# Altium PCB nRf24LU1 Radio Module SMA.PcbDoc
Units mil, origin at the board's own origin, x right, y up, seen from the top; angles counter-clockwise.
Board outline 2945.94 x 691.05 mil, 2 copper layers (Top Layer, Bottom Layer); 43 components, 43 nets, 167 pads, 126 vias.
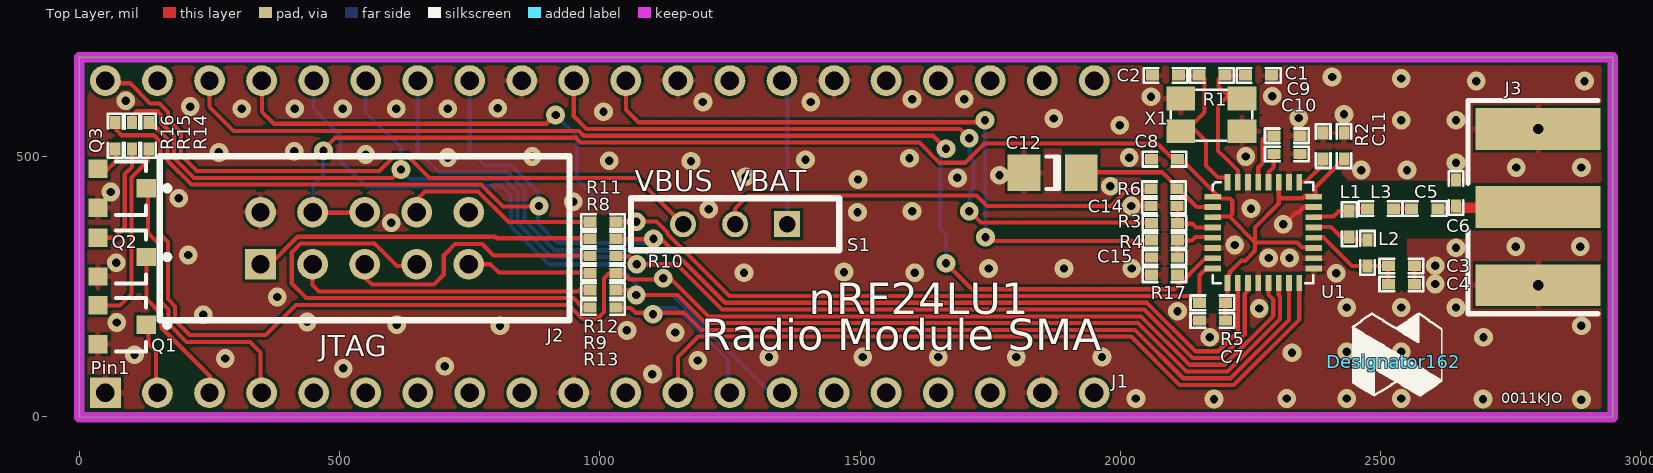
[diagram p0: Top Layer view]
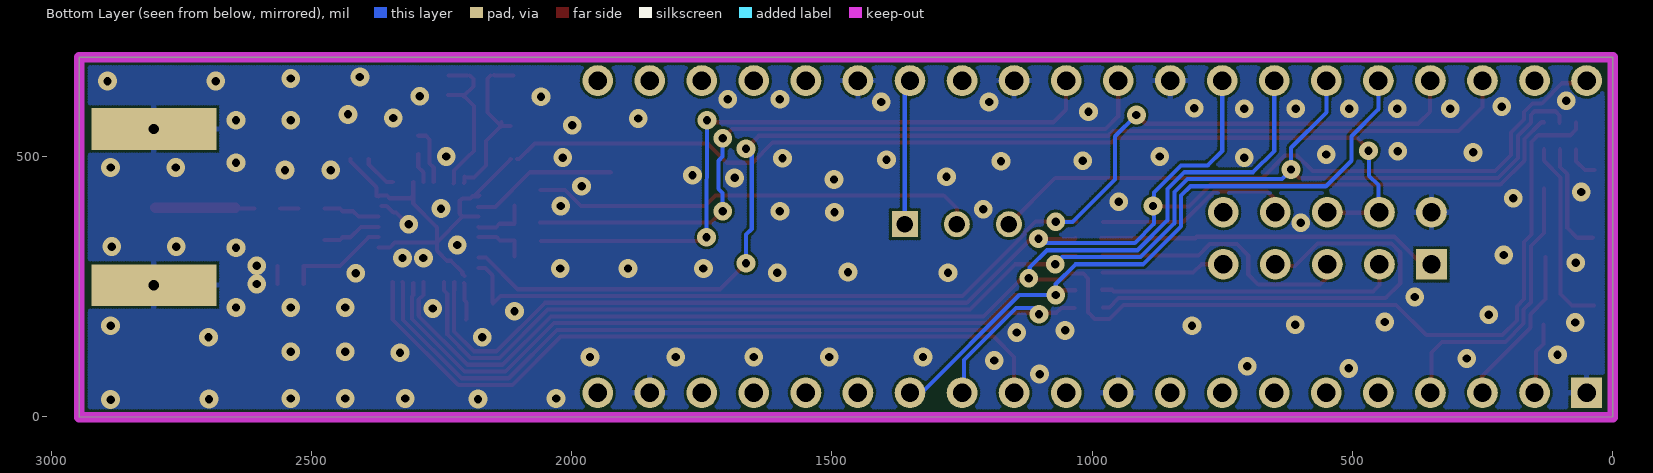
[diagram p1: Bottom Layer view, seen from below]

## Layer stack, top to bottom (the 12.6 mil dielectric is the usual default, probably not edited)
Top Layer: signal copper 1.4
Dielectric: dielectric 12.6, FR-4, Dk 4.8
Bottom Layer: signal copper 1.4

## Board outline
0,0 0,690.53 2945.94,690.53 2945.94,-0.53

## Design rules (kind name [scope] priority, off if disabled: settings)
Clearance [All] p1: gap=5
ComponentClearance [All] p1 off: gap=10 collisioncheckmode=3 verticalgap=10
PolygonConnect PolygonConnect_1 [IsVia and InNet(GND)] p1: connectstyle=Direct reliefconductorwidth=10 reliefentries=4 polygonreliefangle="90 Angle"
PolygonConnect [All] p2: connectstyle=Relief reliefconductorwidth=10 reliefentries=4 polygonreliefangle="90 Angle"
RoomDefinition "nRF24LU1 Radio Module SMA" [InComponentClass('nRF24LU1 Radio Module SMA')] p1 off: confinementstyle=ConfineIn formatcopy=TRUE lockcomponents=FALSE outline 3275,-45 3549,-45 3549,486 3275,486
RoutingVias [All] p1: holewidth=10 width=20 viastyle="Through Hole" minholewidth=6 minwidth=10 maxholewidth=28 maxwidth=50
SolderMaskExpansion [All] p1: expansion=4
TestPointUsage [All] p1: valid=0 allowmultiple=FALSE
Testpoint [All] p1: side=15 testpointundercomponent=TRUE minsize=40 maxsize=100 preferedsize=60 minholesize=0 maxholesize=40 preferedholesize=32 testpointgrid=1 style=1023 order=0123456789
Width [All] p1: maxlimit=50 minlimit=6 preferedwidth=10 toplayer_prefwidth=8 bottomlayer_prefwidth=8 minimp=50.000000 maximp=50.000000 favimp=50.000000
18 further rules are at their usual default settings.

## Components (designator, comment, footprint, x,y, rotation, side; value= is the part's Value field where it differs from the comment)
C1 "NPO, +/-2% 50V" 0402s 2266,656 r0 top
C2 "NPO, +/-2% 50V" 0402s 2087,656 r0 top
C3 "X7R, +/-10% 50V" 0402s 2540,290 r180 top
C4 "NP0 +/-0.25pF, 50V" 0402s 2540,255 r180 top
C5 "NP0 +/-0.1pF, 50V" 0402s 2585,400 r180 top
C6 "NP0 +/-0.1pF, 50V" 0402s 2645,430 r90 top
C7 "X7R, +/-10% 50V" 0402s 2177,185 r180 top
C8 "X7R, +/-10% 50V" 0402s 2085,495 r180 top
C9 "X7R, +/-10% 50V" 0402s 2320,540 r0 top
C10 "X7R, +/-10% 50V" 0402s 2320,505 r0 top
C11 "X7R, +/-10% 50V" 0402s 2430,520 r90 top
C12 "Tantal  10V" C1206 1870,469 r180 top
C14 "NP0, +/-10% 50V" 0402s 2084,405 r180 top
C15 "" 0402s 2085,306 r180 top
Designator162 "Comment" NordicSemi1 2525,106 r180 top
J1 "Elfa 48-155-10" DIP40 50,46 r90 top
J2 "Header 2x5 pin" IDC2X5 548,343 r0 top
J3 "SMA Female" "SMA connector horizontal" 2803,403 r90 top
L1 "Chip inductor +/-5% Murata LQP15" 0402s 2440,370 r270 top
L2 "Chip Inductor +/-5% Murata LQP15" 0402s 2475,315 r90 top
L3 "Chip inductor +/-5% Murata LQP15" 0402s 2500,400 r0 top
Q1 "BC847C" SOT23 82,177 r270 top
Q2 "BC847C" SOT23 82,307 r270 top
Q3 "BC847C" SOT23 82,439 r270 top
R1 "5%" 0402s 2176,656 r180 top
R2 "1%" 0402s 2390,520 r270 top
R3 "5%" 0402s 2085,372 r180 top
R4 "5%" 0402s 2085,339 r180 top
R5 "5%" 0402s 2177,219 r0 top
R6 "5%" 0402s 2084,438 r180 top
R8 "" 0402s 1006,342 r180 top
R9 "" 0402s 1006,243 r180 top
R10 "" 0402s 1006,309 r180 top
R11 "" 0402s 1006,375 r180 top
R12 "" 0402s 1006,276 r180 top
R13 "" 0402s 1006,210 r180 top
R14 "5%" 0402s 133,540 r270 top
R15 "5%" 0402s 101,540 r270 top
R16 "5%" 0402s 69,540 r270 top
R17 "5%" 0402s 2085,273 r0 top
S1 "ELFA 35-365-21" "SW mini2" 1360,370 r180 top
U1 "nRF24LU1" QFN32L/5x5 2178,257 r0 top
X1 "TSX4025 16MHz, CL=9pF" BT-XTAL 2175,580 r180 top

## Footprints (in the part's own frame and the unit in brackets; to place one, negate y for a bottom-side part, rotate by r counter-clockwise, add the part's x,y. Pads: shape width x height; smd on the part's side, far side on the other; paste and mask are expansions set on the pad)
0402s [mil]
  rect 25x20 smd: 1(-25,0) 2(25,0)
  silkscreen extent -42,-14 42,14
BT-XTAL [mm]
  rect 1.4x1.15 smd: 1(-1.498,-0.801) 2(1.498,-0.801) 3(1.498,0.801) 4(-1.498,0.801)
  silkscreen extent -2,-1.23 1.98,1.26
C1206 [mm] "Chip Capacitor; Body 3.2 x 1.6 mm (LxW typ)"
  rect 1.6x1.8 smd: 1(-1.4,0) 2(1.4,0)
  silkscreen extent -0.3,-0.8 0.3,0.8
DIP40 [mm]
  rect 1.5x1.5 hole 0.9: 1(0,0)
  round 1.5 hole 0.9: 2(0,-2.54) 3(0,-5.08) 4(0,-7.62) 5(0,-10.16) 6(0,-12.7) 7(0,-15.24) 8(0,-17.78) 9(0,-20.32) 10(0,-22.86) 11(0,-25.4) 12(0,-27.94) 13(0,-30.48) 14(0,-33.02) 15(0,-35.56) 16(0,-38.1) 17(0,-40.64) 18(0,-43.18) 19(0,-45.72) 20(0,-48.26) 21(15.24,-48.26) 22(15.24,-45.72) 23(15.24,-43.18) 24(15.24,-40.64) 25(15.24,-38.1) 26(15.24,-35.56) 27(15.24,-33.02) 28(15.24,-30.48) 29(15.24,-27.94) 30(15.24,-25.4) 31(15.24,-22.86) 32(15.24,-20.32) 33(15.24,-17.78) 34(15.24,-15.24) 35(15.24,-12.7) 36(15.24,-10.16) 37(15.24,-7.62) 38(15.24,-5.08) 39(15.24,-2.54) 40(15.24,0)
IDC2X5 [mm]
  rect 1.5x1.5 hole 0.9: 1(-5.08,-1.27)
  round 1.5 hole 0.9: 2(-5.08,1.27) 3(-2.54,-1.27) 4(-2.54,1.27) 5(0,-1.27) 6(0,1.27) 7(2.54,-1.27) 8(2.54,1.27) 9(5.08,-1.27) 10(5.08,1.27)
  silkscreen extent -10,-4 10,4
NordicSemi1 [mil]
  silkscreen extent -94,-94 80,66
QFN32L/5x5 [mm]
  rect 0.8x0.28 smd: 1(-0.001,4.205) 2(-0.001,3.705) 3(-0.001,3.205) 4(-0.001,2.705) 5(-0.001,2.205) 6(-0.001,1.705) 7(-0.001,1.205) 8(-0.001,0.705) 17(4.917,0.705) 18(4.917,1.205) 19(4.917,1.705) 20(4.917,2.205) 21(4.917,2.705) 22(4.917,3.205) 23(4.917,3.705) 24(4.917,4.205)
  rect 0.28x0.8 smd: 9(0.71,0) 10(1.21,0.004) 11(1.71,0.004) 12(2.21,0.004) 13(2.71,0.004) 14(3.21,0.004) 15(3.71,0.004) 16(4.21,0.004) 25(4.21,4.921) 26(3.71,4.921) 27(3.21,4.921) 28(2.71,4.921) 29(2.21,4.921) 30(1.71,4.921) 31(1.21,4.921) 32(0.71,4.921)
  silkscreen extent 0,-0.01 4.9,4.92
"SMA connector horizontal" [mil]
  rect 80x240 smd: 1(0,0)
  rect 80x240 hole 20: 2(-150,0) 2(150,0)
  silkscreen extent -205,-115 205,135
SOT23 [mm] "SOT-23; 3 Leads; Body 3.1 x 2.5 mm, inc. leads (LxW max), Alternate Lead Configuration"
  rect 0.9x0.95 smd: 1(0,1.175) 2(0.95,-1.175) 3(-0.95,-1.175)
  silkscreen extent -1.3,-0.3 1.3,2.33
"SW mini2" [mil]
  rect 50x50 hole 32: 1(0,0)
  round 50 hole 32: 2(100,0) 3(200,0)
  silkscreen extent -100,-50 300,50

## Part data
C1 C2 C3 C4 C5 C6 C7 C8 C9 C10 C11 C14 C15: library part CAP
C12: library part "Cap Pol3", "Polarized Capacitor (Surface Mount)"
J1: library part 40PIN
J2: library part "Header 6", "Header, 6-Pin"
J3: library part BNC, "BNC Elbow Connector"
L1 L2 L3: library part INDUCTOR1
Q1 Q2 Q3: library part NPN, "NPN Bipolar Transistor"
R1 R2 R3 R4 R5 R6 R8 R9 R10 R11 R12 R13 R14 R15 R16 R17: library part RES2
S1: library part SW-SPDT, "SPDT Subminiature Toggle Switch, Right Angle Mounting, Vertical Actuation"
U1: library part nRF24LU01, "nRF24LU01"
X1: library part BT-XTAL

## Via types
v1: diameter 36, hole 16, Top Layer to Bottom Layer, tented both sides, 125 vias
v2: diameter 35.98, hole 15.98, Top Layer to Bottom Layer, tented both sides, 1 vias

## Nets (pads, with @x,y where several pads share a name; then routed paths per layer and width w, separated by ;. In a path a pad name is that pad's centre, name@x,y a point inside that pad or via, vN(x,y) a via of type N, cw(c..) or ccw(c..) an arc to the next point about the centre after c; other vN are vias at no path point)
CSN/TDO: J1.14 J1.36 R9.1 U1.14 | length 2706.7
  Top Layer w8: R9.1@1032,243 1061,243 v1(1070,234) 1149,234 1203,180 2034,180 2127,87 2206,87 2307,188 2307,231 2304,234 ; 2304.53,234.53 U1.14@2304.53,257.15
  Bottom Layer w7.99: 829,366 829,425
  Bottom Layer w8: J1.36@450,645 450,591 502,539 502,492 551,443 811,443 829,425 ; 829,366 902,293 1032,293 1070,255 v1(1070,234) 1140,234 1329,45 1348,45 J1.14@1350,47
D+: J1.31 R3.2 | length 1351.8
  Top Layer w8: J1.31@950,645 950,577.5 974.5,553 1692,553 v1(1710,535) ; v1(1710,395) 1732,373 R3.2@2061,373
  Bottom Layer w8: v1(1710,395) 1710,430 1718,438 1718,492 1710,500 v1(1710,535)
D-: J1.30 R4.2 | length 1306.3
  Top Layer w8: J1.30@1050,645 1050,590 1074,566 1736,566 v1(1740,570) ; v1@1738,347 1747,338 R4.2@2059,338
  Bottom Layer w8: v1(1740,570) v1@1740.9,345
  other v1: 1741,345
GND: C1.2 C2.1 C3.1 C4.1 C6.2 C7.2 C8.2 C9.2 C10.2 C11.2 C12.2 C14.2 C15.2 J1.1 J1.10 J1.19 J1.26 J1.29 J1.32 J2.2 J3.2 Q1.2 Q2.2 Q3.2 R2.1 R17.1 U1.6 U1.12 U1.17 U1.18 U1.23 U1.26 U1.30 X1.2 X1.4 | length 85.4
  Top Layer w8: v1@2325,380 2337.53,392.53 2342.89,392.53 2355.36,405 U1.23@2365,405 ; C4.1 C3.1
  other v1: 2886,33 2180,34 2697,34 2030,35 2320,35 2435,35 2540,35 1101,82 507,93 702,97 1188,108 280,112 1325,115 1505,115 1650,115 1800,115 1965,115 106,119 2330,123 2435,125 2540,125 2172,153 2698,153 1145,162 1052,166 808,175 2886,175 610,177 72,181 438,182 238,196 2110,203 2267,208 2435,210 2540,210 2645,210 380,230 2605,255 2415,276 1277,277 1605,277 1469,278 1747,285 1892,285 2022,285 2605,290 2285,305 2325,305 209,311 2645,325 2760,327 2884,327 2220,330 2313,370 599,373 1495,393 1600,395 1209,399 2251,400 2021,405 949,413 191,420 60,432 1981,443 1496,456 1687,459 1280,461 1768,464 2463,474 2551,474 2761,479 2886,479 2645,488 1175,491 1018,492 1395,494 1595,497 708,498 2017,498 870,500 2241,500 550,504 268,508 413,510 1999,560 2540,570 2645,570 1872,573 2343,574 2430,581 1007,586 312,592 414,592 506,592 609,592 708,592 804,593 213,596 1198,605 1405,605 89,607 1600,610 1700,610 2059,615 2292,616 2684,645 2892,645 2540,650 2407,653
  other v2: 71,296
LED1: J1.2 Q1.1 | length 135.8
  Top Layer w8: Q1.1@133,177 133,140 147,126 J1.2@147,47
LED2: J1.3 Q2.1 | length 310.9
  Top Layer w8: Q2.1@129,307 129,226 158,197 158,171 252,77 J1.3@252,47
LED3: J1.4 Q3.1 | length 552.6
  Top Layer w8: Q3.1@132,438 132,353 157,328 157,220 171,206 171,179 206,144 328,144 348.26,123.74 348.26,48.26 J1.4@347,47
LED4: J1.5
MISO/TDI: J1.34 R12.1 R16.1 U1.13 | length 3618.5
  Top Layer w8: R16.1@70,565 70,552 81,541 143,541 156,528 156,350 170,336 170,226 184,212 184,185 212,157 358,157 416,215 940,215 967,188 995,188 1008,201 1008,266 1017,275 1046,275 1057,264 1138,264 1209,193 2040,193 2133,100 2200,100 2294,194 2294,225 2284.84,234.16 U1.13@2284.84,258.89
  Bottom Layer w8: J1.34@650,645 650,511 691,470 822.75,470 855,437.75 855,377.75 912.75,320 1087,320 1120,287 v1@1120,275
  other v1: 1122,266
MOSI/TMS: J1.35 R10.1 R15.1 U1.11 | length 2805.3
  Top Layer w7.99: R15.1@102,565 102,579 110,587 150,587
  Top Layer w8: 150,587 157,580 157,565 182,540 182,497.44 220.44,459 602,459 v1@618.5,475.5 ; R10.1 1056,309 1072,293 1148,293 1235,206 2046,206 2139,113 2194,113 2239,158 2239,236.06 2245.47,242.53 U1.11@2245.47,258.89
  Bottom Layer w8: J1.35@550,645 550,585 618,517 v1@618,476 ; v1@617,476 617,475 635,457 817,457 842,432 842,372 907,307 1058,307 v1@1074,291
  other v1: 1071,293 618,475
NetC1_1: C1.1 R1.1 U1.31 X1.1 | length 309.2
  Top Layer w8: R1.1@2196,656 2189,649 2189,635 X1.1@2208,616 ; R1.1 C1.1@2237,656 ; 2202,497 2188,511 2188,597 2209,618 X1.1@2238,618 ; 2203,496 2226,473 2226,449 U1.31@2227,448
NetC2_2: C2.2 R1.2 U1.32 X1.3 | length 335.8
  Top Layer w8: C2.2 2148,656 R1.2@2149,657 ; X1.3@2118,559 2136,559 2165,530 2165,483 2188,460 2206,460 2206,450 U1.32@2207,449 ; X1.3@2135,566 2135,558 2162,585 2162,650 R1.2@2156,656 ; U1.32@2206.1,451.11 U1.32@2206.1,461.9
NetC3_2: C3.2 C4.2 L2.1 U1.20 | length 201.7
  Top Layer w8: U1.20@2371.11,345.16 2389.84,345.16 2445,290 C3.2 C4.2
NetC5_1: C5.1 C6.1 J3.1 | length 191.1
  Top Layer w8: C5.1 2640,400 C6.1
  Top Layer w20: C6.1@2646,402 J3.1@2800,402
NetC5_2: C5.2 L3.2 | length 35
  Top Layer w8: L3.2 C5.2
NetC9_1: C9.1 U1.29 | length 110
  Top Layer w8: U1.29@2265.16,451.11 2265.16,479.16 2273,487 2273,533 2280,540 C9.1
NetC10_1: C10.1 U1.28 | length 58.1
  Top Layer w8: U1.28@2284.84,451.11 2284.84,469.84 2295,480 C10.1
NetC12_1: C12.1 R6.1 U1.2 | length 282.8
  Top Layer w8: C12.1@1925,470 2080,470 2147,403 U1.2@2180,403
NetC14_1: C14.1 R3.1 U1.4 | length 107.1
  Top Layer w8: C14.1@2110,406 2110,371 2138.68,371 2145.68,364 U1.4@2177.96,364 ; U1.4@2178.05,364 U1.4@2178.89,364.84
NetC15_1: C15.1 R4.1 U1.5 | length 100.4
  Top Layer w8: C15.1@2110,308 R4.1 ; R4.1@2112,339 2138,339 2144.16,345.16 U1.5@2178.89,345.16
NetJ2_1: J2.1 R8.2 | length 657.6
  Top Layer w8: J2.1@349,292 365,292 419,346 799,346 802,343 R8.2@983,343
NetJ2_3: J2.3 R9.2 | length 576.2
  Top Layer w8: J2.3@448,290 448,253 460,241 959,241 962,244 R9.2@981,244
NetJ2_5: J2.5 R10.2 | length 520.1
  Top Layer w8: J2.5@550,288 550,266 562,254 681,254 700,273 700,310 722,332 774,332 796,310 R10.2@980,310
NetJ2_7: J2.7 R13.2 | length 916.9
  Top Layer w8: J2.7@650,290 610,290 567,333 425,333 408,316 408,256 436,228 949,228 967,210 R13.2@979,210
NetJ2_8: J2.8 R11.2 | length 391.3
  Top Layer w8: J2.8@653,389 649,393 649,418 664,433 766,433 825,374 R11.2@979,374
NetJ2_9: J2.9 R12.2 | length 236
  Top Layer w8: J2.9@751,292 752,293 790,293 806,277 R12.2@980,277
NetL1_1: L1.1 L3.1 U1.22 | length 110.3
  Top Layer w8: U1.22@2371.11,384.53 2409.53,384.53 2420,395 L1.1 2445,400 L3.1
NetL1_2: L1.2 L2.2 U1.21 | length 114.2
  Top Layer w8: U1.21@2371.11,364.84 2405.16,364.84 2425,345 L1.2 2445,340 L2.2
NetQ1_2: Q1.3 R14.2 | length 364.4
  Top Layer w8: Q1.3@36,214 78,214 100,236 100,460 132,492 R14.2@132,514
NetQ2_2: Q2.3 R15.2 | length 213.7
  Top Layer w8: Q2.3@38,344 68,344 87,363 87,465.94 101,479.94 R15.2@101,514
NetQ3_2: Q3.3 R16.2 | length 64
  Top Layer w8: Q3.3@35,474 53,474 70,491 R16.2@70,513
NetR2_2: R2.2 U1.25 | length 70.1
  Top Layer w8: U1.25@2343.9,451.11 2356.11,451.11 2390,485 R2.2
NetR6_2: R6.2 S1.2 | length 861.5
  Top Layer w8: S1.2 1260,400 1285,425 1724,425 1744,405 1981.91,405 2012.91,436 R6.2@2060,436
P0.4: J1.13 R13.1 U1.15 | length 1714.1
  Top Layer w8: R13.1@1034,209 1059.31,209 1068.31,200 1162,200 1195,167 2028,167 2121,74 2211.94,74 2324,186.06 2324,258 U1.15@2325,259
  Bottom Layer w8: v1@1102,209 1146,209 1246,109 J1.13@1246,46
  other v1: 1102,197
P0.5: J1.12 U1.16 | length 1442.8
  Top Layer w8: J1.12@1150,45 1150,115 1189,154 2021,154 2114,61 2217.94,61 2344,187.06 2344,235.8 2343.9,235.9 U1.16@2343.9,258.89
PROG: J1.38 R17.2 U1.7 | length 2288
  Top Layer w8: J1.38@250,645 250,595 296,549 960,549 969,540 1641,540 ; 1640,540 v1(1665,515) ; v1(1665,295) 1715,245 2104,245 2164.79,305.79 U1.7@2178.89,305.79
  Bottom Layer w8: v1(1665,295) 1665,350 1654,361 1654,504 v1(1665,515)
RESET: J1.37 R5.1 R11.1 U1.8 | length 2203.6
  Top Layer w7.99: J1.37@351,644 351,586 374,563 897,563 v1@914.5,580.5 ; R5.1@2152,220 2152,272 2166.1,286.1 U1.8@2178.89,286.1
  Top Layer w8: R11.1@1030,375 1109,375 1130,354 1130,350.94 1248.94,232 2137,232 R5.1@2151,218
  Bottom Layer w7.99: v1(915,580) 956,539 956,456 1038,374 1069,374 1069,372 v1@1071,374
  other v1: 1070,375
SCK/TCK: J1.33 R8.1 R14.1 U1.10 | length 2838.9
  Top Layer w7.99: 814,404 v1@884,404
  Top Layer w8: R14.1@132,566 137,566 169,534 169,492 215,446 772,446 814,404 ; R8.1@1032,343 1034,341 1119,341 1241,219 2051.61,219 2144.61,126 2188,126 2226,164 2226,242 2225.79,242.21 U1.10@2225.79,258.89
  Bottom Layer w8: J1.33@750,645 750,511 778,483 829,483 881,431 881,371 918,334 1094,334 v1@1104,344
  other v1: 1103,342 883,405
VBAT: J1.40 S1.3 | length 1278.9
  Top Layer w8: J1.40@52,641 97,641 136,602 153.75,602 170,585.75 170,571 195,546 195,503 226,472 576.19,472 606.19,502 630,502 673,459 1071,459 S1.3
VBUS: J1.27 S1.1 | length 286.2
  Top Layer w8: S1.1 S1.1@1365,365
  Bottom Layer w8: J1.27@1350,645 1360,635 S1.1
VDD: J1.28
VDD_NRF: C7.1 C8.1 C11.1 J2.4 J2.6 R5.2 U1.1 U1.3 U1.9 U1.19 U1.24 U1.27 | length 2789.8
  Top Layer w8: J2.4@447,392 J2.6@552,392 ; v1@469,512 469,514 491,536 954,536 963,527 1614,527 1653,488 1701.75,488 1738.75,525 2071,525 2101,495 C8.1@2105,495 ; C8.1@2117,495 2187,425 2177.79,425 2178.89,423.9 2190.59,423.9 2194.76,419.72 2210.28,419.72 2215,415 2215,390 2209.53,384.53 ; U1.3@2178.89,384.53 2209.53,384.53 ; C7.1@2203,187 2202,188 2202,220 2206,224 2206,256 U1.9@2207,257 ; U1.9@2206.1,270.59 2210.28,274.76 2210.28,277.99 2231.98,299.69 2239.69,299.69 2259.06,319.06 2259.06,364.06 2304.53,409.53 U1.27@2304.53,451.11 ; 2304.53,425.47 2310.23,419.77 2349.77,419.77 2355,425 2370.01,425 U1.24@2371.11,423.9 ; U1.19@2371.11,325.47 2349.53,325.47 2340,335 2259.06,335 2209.53,384.53 ; U1.24@2375,424 2375,441 2425,491 C11.1@2425,495
  Bottom Layer w8: J2.4@450,390 450,445 468,463 v1@468,512
  other v1: 469,511
VDD_REG_RF: J1.39
pads on no net: J1.6 J1.7 J1.8 J1.9 J1.11 J1.15 J1.16 J1.17 J1.18 J1.20 J1.21 J1.22 J1.23 J1.24 J1.25 J2.10

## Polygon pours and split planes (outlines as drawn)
GND on Top Layer "Top Layer-GND" (hatched 90Degree grid 5 track 6, remove dead copper, pour order 1000): -70,730 2923,730 2923,-50 -64.52,-50
GND on Bottom Layer "Bottom Layer-GND" (hatched 90Degree grid 5 track 7.99, remove dead copper, pour order 1001): 2926,-85 2926,750 -80,750 -80,-80

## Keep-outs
Keep-Out Layer:
  lines w20: 0.01,-0.53 0,0 0,690.53 2945.94,690.53 2945.94,-0.53 0.01,-0.53

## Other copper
Top Layer:
  pour cut-out: 2160,195.5 2194,195.5 2194,270.5 2160,270.5
  pour cut-out: 2401,512 2419,512 2419,480 2401,480
  pour cut-out: 2389,432 2353,432 2353,439 2394,480 2418,480 2439,456 2438,456 2439,456 2438,456 2670,456 2670,340 2553,340 2553,240 2495,240 2495,270 2460,270 2415,320 2389.84,345.16 2390.07,430.07
  pour cut-out: 2119,593 2119,567 2140,567 2140,593
  pour cut-out: 2231,590 2231,570 2207,570 2207,590
  pour cut-out: 993,390 1018,390 1018,196 993,196

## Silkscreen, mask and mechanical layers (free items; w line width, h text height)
Top Overlay:
  text "VBUS  VBAT" at 1067,433 h40
  text "nRF24LU1" at 1401,197 h60
  text "Radio Module SMA" at 1195,128 h60
  text "JTAG" at 461,116 h40
  text "0011KJO" at 2732,26 h20
Mechanical 1:
  lines w20: 0,0 0,690 2946,690 2946,0 0,0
